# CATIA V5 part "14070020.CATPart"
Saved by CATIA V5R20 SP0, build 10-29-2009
Part number: 14070020
Definition: NONE
Nomenclature: 14070020
Source: Unknown
Description: 14070020
Bounding box of the stored display mesh (mm): x -10 to 40, y -49 to 39.1, z -39.1 to 39.1
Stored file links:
  C:\Users\Utente\Desktop\IO LAVORO\3D X SITO CF\X SITO\PLASTICA\RF2\14070020.CATPart
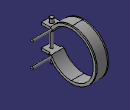
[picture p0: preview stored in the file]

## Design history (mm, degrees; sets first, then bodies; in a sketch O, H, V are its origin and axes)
Body1 "14070020" (main body)
  Solid1: solid without history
